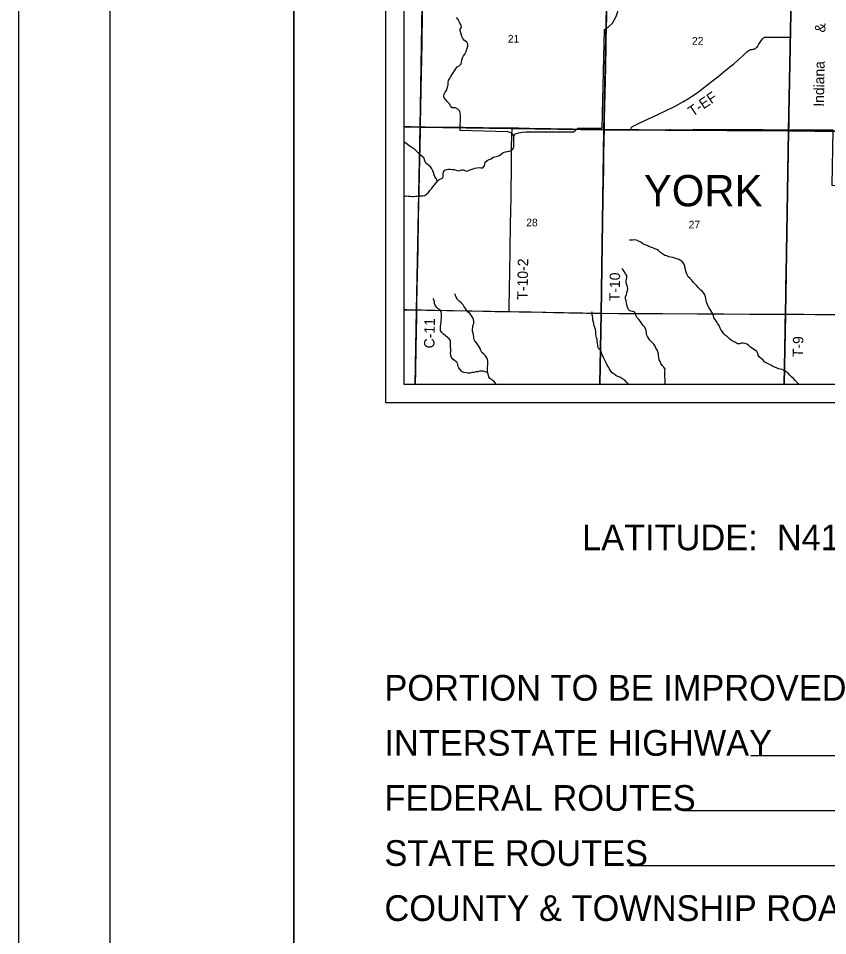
# Model space of a CAD drawing. Extents: x 0 to 42, y 0 to 22.
# Drawn here: x 0 to 4.409, y 11.097 to 16.093 of the extents above; entities that cross this region are included whole.
import ezdxf

# ---------------------------------------------------------------- set-up
doc = ezdxf.new("R2010")
doc.units = 0
for name, color, linetype in [('Default', 7, 'Continuous'), ('GM_X_County_Road', 7, 'Continuous'), ('GM_X_County_Road_Text', 7, 'Continuous'), ('GM_X_Interchange_Ramps', 7, 'Continuous'), ('GM_X_Minor_River', 7, 'Continuous'), ('GM_X_Rail_Line_Text', 7, 'Continuous'), ('GM_X_Section', 7, 'Continuous'), ('GM_X_Section_Text', 7, 'Continuous'), ('GM_X_Township_Road', 7, 'Continuous'), ('GM_X_Township_Road_Text', 7, 'Continuous'), ('GM_X_Township_Text', 7, 'Continuous'), ('SH_Border', 7, 'Continuous'), ('SH_Cut_Line', 7, 'Continuous'), ('SH_Data', 7, 'Continuous'), ('SH_Text', 7, 'Continuous')]:
    doc.layers.add(name, color=color, linetype=linetype)

msp = doc.modelspace()

# ---------------------------------------------------------------- linework, layer by layer
at = {"layer": 'Default'}
for points in [[(2.1, 16.5057), (2.1, 15.5023), (2.1886, 15.5005), (2.2056, 16.5033)], [(2.1, 15.5023), (2.1, 14.5047), (2.1694, 14.5034), (2.1886, 15.5005)], [(2.1, 14.5047), (2.1, 14.1), (2.1621, 14.1), (2.1694, 14.5034)], [(2.1621, 14.1), (3.1686, 14.1), (3.1749, 14.4863), (2.1694, 14.5034)], [(3.1686, 14.1), (4.1714, 14.1), (4.179, 14.4795), (3.1749, 14.4863)], [(4.1714, 14.1), (5.1749, 14.1), (5.1819, 14.4731), (4.179, 14.4795)]]:
    msp.add_lwpolyline(points, close=True, dxfattribs=at)
at = {"layer": 'GM_X_County_Road'}
for points in [[(2.1907, 15.5024), (2.1914, 15.5243), (2.1926, 15.5989), (2.1946, 15.7077), (2.1992, 15.9595), (2.2004, 16.0154), (2.2015, 16.0651), (2.2023, 16.1211), (2.2044, 16.2423), (2.2053, 16.2858), (2.206, 16.3231), (2.2069, 16.3852), (2.2082, 16.4381), (2.209, 16.4644)], [(2.1, 15.5053), (2.1389, 15.5044), (2.1762, 15.503), (2.1907, 15.5024)], [(2.1712, 14.5055), (2.1716, 14.5423), (2.173, 14.6231), (2.1773, 14.8376), (2.1806, 15.0023), (2.1821, 15.0862), (2.1832, 15.1515), (2.1871, 15.3317), (2.1881, 15.3938), (2.1901, 15.484), (2.1907, 15.5024)], [(2.1907, 15.5024), (2.2174, 15.502), (2.4225, 15.4997), (2.6432, 15.4971), (2.6916, 15.4967)], [(2.6916, 15.4967), (2.696, 15.4966), (2.7239, 15.4961), (2.783, 15.4949), (3.0191, 15.4913), (3.1925, 15.4887)], [(3.1925, 15.4887), (3.2118, 15.4885), (3.3375, 15.4878)], [(3.3375, 15.4878), (3.3796, 15.4876), (3.507, 15.4869), (3.5381, 15.4869), (3.5475, 15.4872), (3.5536, 15.4874), (3.5659, 15.4867), (3.5846, 15.4864), (3.6467, 15.4864), (3.7275, 15.486), (3.8363, 15.4853), (4.0663, 15.4846), (4.1222, 15.4838), (4.1978, 15.484)], [(4.1978, 15.484), (4.272, 15.4831), (4.3155, 15.4829), (4.3683, 15.4821), (4.5237, 15.4804), (4.5922, 15.48), (4.6232, 15.4796), (4.9031, 15.4763), (4.9901, 15.4754), (5.0461, 15.4746), (5.1612, 15.4735), (5.2731, 15.4735), (5.3446, 15.474), (5.4783, 15.4751), (5.6991, 15.4769), (5.7488, 15.4774), (5.8701, 15.4786), (5.9447, 15.4796), (5.9547, 15.4798)], [(2.1, 14.5072), (2.116, 14.5068), (2.1501, 14.5057), (2.1712, 14.5055)], [(2.164, 14.1), (2.1653, 14.1725), (2.1674, 14.303), (2.1702, 14.4678), (2.1712, 14.5055)], [(2.1712, 14.5055), (2.1998, 14.5051), (2.2216, 14.5046), (2.3335, 14.5026), (2.3614, 14.5018), (2.5324, 14.4985), (2.5976, 14.4974), (2.6473, 14.4966), (2.6734, 14.4961)], [(2.6734, 14.4961), (2.6815, 14.4959), (2.7281, 14.4952), (2.7716, 14.4943), (2.7932, 14.494), (2.9176, 14.4915), (2.9984, 14.4901), (3.0978, 14.4882), (3.1757, 14.4867)], [(3.1757, 14.4867), (3.2688, 14.4862), (3.3216, 14.4859), (3.5082, 14.485), (3.6978, 14.484), (3.7444, 14.4837), (3.7848, 14.4837), (3.8128, 14.4834), (3.9837, 14.4826), (4.08, 14.4821), (4.111, 14.4818), (4.1791, 14.4815)], [(4.1791, 14.4815), (4.2477, 14.4811), (4.2788, 14.4811), (4.3409, 14.4806), (4.4031, 14.4801), (4.4621, 14.4799), (4.5461, 14.4791), (4.6145, 14.479), (4.6829, 14.4784), (4.7513, 14.4781), (4.8383, 14.4775), (4.9876, 14.4765), (5.0964, 14.476), (5.2021, 14.4755), (5.2798, 14.4758), (5.4757, 14.4765), (5.6125, 14.4769), (5.6747, 14.4771), (5.8208, 14.477), (5.9265, 14.4775), (5.9296, 14.4775), (5.9383, 14.4777)]]:
    msp.add_lwpolyline(points, dxfattribs=at)
at = {"layer": 'GM_X_Interchange_Ramps'}
msp.add_lwpolyline([(2.1, 18.5138), (2.1, 14.1), (6.182, 14.1), (6.1883, 14.4744), (6.2063, 15.4779), (6.2205, 16.2146)], dxfattribs=at)
at = {"layer": 'GM_X_Minor_River'}
for points in [[(2.699, 15.4505), (2.7058, 15.4647), (2.7257, 15.4696), (2.7455, 15.4741), (2.7645, 15.4756), (2.7816, 15.4752), (3.0251, 15.4747), (3.0476, 15.495), (3.1804, 15.4958), (3.1937, 16.0334), (3.2149, 16.047), (3.2374, 16.0677), (3.2576, 16.1033), (3.2748, 16.1595), (3.2747, 16.2191), (3.2728, 16.2518), (3.2652, 16.2815), (3.2721, 16.3019), (3.2839, 16.3195), (3.3331, 16.3958), (3.3403, 16.4932), (3.36, 16.4927)], [(2.4081, 15.5655), (2.4045, 15.5885), (2.3948, 15.5982), (2.3806, 15.605), (2.3631, 15.606), (2.3535, 15.6173), (2.3462, 15.6288), (2.3381, 15.6389), (2.3292, 15.6493), (2.3192, 15.6605), (2.3187, 15.67), (2.3197, 15.681), (2.326, 15.6907), (2.3319, 15.7009), (2.3364, 15.7129), (2.3401, 15.7238), (2.3411, 15.7337), (2.3417, 15.7435), (2.3438, 15.7545), (2.3482, 15.7643), (2.3557, 15.7762), (2.3616, 15.786), (2.3683, 15.7968), (2.3762, 15.8073), (2.3829, 15.8178), (2.3911, 15.8286), (2.4011, 15.8344), (2.4123, 15.8452), (2.4148, 15.855), (2.4158, 15.8648), (2.4195, 15.878), (2.4251, 15.8885), (2.4325, 15.8982), (2.4385, 15.9091), (2.4414, 15.9204), (2.4443, 15.9306), (2.448, 15.9419), (2.449, 15.9529), (2.4432, 15.9629), (2.4309, 15.9723), (2.4209, 15.9828), (2.4166, 15.9939), (2.411, 16.0145), (2.407, 16.0244), (2.4073, 16.0347), (2.4136, 16.0456), (2.4127, 16.0558), (2.4046, 16.0662), (2.4018, 16.0766), (2.396, 16.0869), (2.3867, 16.0981)], [(2.6984, 15.3935), (2.699, 15.4505), (2.6955, 15.4612), (2.6888, 15.467), (2.6779, 15.4722), (2.667, 15.4747), (2.4076, 15.482), (2.4081, 15.5655)], [(4.6965, 15.0998), (4.6927, 15.1519), (4.6903, 15.1577), (4.686, 15.1604), (4.6788, 15.1601), (4.5688, 15.1618), (4.5678, 15.1808), (4.4327, 15.1827), (4.4387, 15.484), (3.6765, 15.4885)], [(2.2828, 15.2062), (2.2741, 15.222), (2.2694, 15.2316), (2.2658, 15.2415), (2.2623, 15.253), (2.2587, 15.263), (2.2533, 15.2745), (2.2444, 15.2845), (2.2352, 15.2942), (2.2255, 15.3017), (2.2155, 15.3114), (2.2131, 15.3228), (2.2103, 15.3324), (2.2002, 15.3402), (2.1898, 15.3495), (2.1805, 15.3592), (2.1701, 15.3682), (2.1594, 15.3783), (2.1489, 15.3861), (2.1287, 15.3995), (2.1175, 15.4073), (2.1056, 15.4163), (2.1, 15.4203)], [(2.1, 15.1223), (2.101, 15.1226), (2.1128, 15.1262), (2.1238, 15.1244), (2.1337, 15.1242), (2.1435, 15.1236), (2.1534, 15.1237), (2.1629, 15.1243), (2.1735, 15.1252), (2.1853, 15.1257), (2.1948, 15.1259), (2.2043, 15.1264), (2.2142, 15.1288), (2.2242, 15.1351), (2.2351, 15.1443), (2.2414, 15.1548), (2.25, 15.1652), (2.2582, 15.1761), (2.2668, 15.1861), (2.275, 15.1962), (2.2828, 15.2062), (2.2917, 15.2159), (2.3024, 15.2187), (2.3124, 15.2246), (2.3146, 15.2348), (2.314, 15.2446), (2.3166, 15.2564), (2.3229, 15.2665), (2.3329, 15.27), (2.3428, 15.2725), (2.3537, 15.2711), (2.3636, 15.2705), (2.3746, 15.2706), (2.3851, 15.2658), (2.3949, 15.2626), (2.4056, 15.2654), (2.4151, 15.2686), (2.425, 15.2683), (2.4355, 15.262), (2.4457, 15.2618), (2.4564, 15.2657), (2.4675, 15.2704), (2.4775, 15.2729), (2.4874, 15.2772), (2.4977, 15.2789), (2.5103, 15.2809), (2.5201, 15.2795), (2.5296, 15.2793), (2.5385, 15.2889), (2.5414, 15.2991), (2.5436, 15.3093), (2.5537, 15.3186), (2.564, 15.3241), (2.5763, 15.3283), (2.5863, 15.3368), (2.5963, 15.3397), (2.61, 15.3431), (2.6219, 15.3471), (2.6319, 15.3552), (2.6416, 15.3618), (2.6534, 15.3657), (2.6637, 15.3689), (2.6732, 15.3698), (2.6836, 15.373), (2.6936, 15.3811), (2.6984, 15.3935)], [(4.1936, 14.1609), (4.1835, 14.1687), (4.1738, 14.1731), (4.1614, 14.1798), (4.1512, 14.1831), (4.1406, 14.1844), (4.1294, 14.1889), (4.1196, 14.1933), (4.1091, 14.1992), (4.0986, 14.2044), (4.0889, 14.2099), (4.0772, 14.2151), (4.0664, 14.2214), (4.0575, 14.2311), (4.0463, 14.2397), (4.0367, 14.2486), (4.0308, 14.2583), (4.0292, 14.2682), (4.0226, 14.2793), (4.011, 14.2876), (4.0009, 14.2935), (3.9894, 14.3028), (3.9782, 14.313), (3.9685, 14.3177), (3.9587, 14.3221), (3.9482, 14.3243), (3.9387, 14.3241), (3.9283, 14.3205), (3.9185, 14.3211), (3.9076, 14.3271), (3.8956, 14.3338), (3.8844, 14.3394), (3.8732, 14.3495), (3.8636, 14.358), (3.8531, 14.3651), (3.8435, 14.3756), (3.8362, 14.3856), (3.8295, 14.3953), (3.8233, 14.4053), (3.8176, 14.4194), (3.8102, 14.4291), (3.8033, 14.4414), (3.7967, 14.4522), (3.7883, 14.4626), (3.787, 14.4733), (3.7838, 14.4832), (3.7784, 14.4932), (3.7718, 14.5028), (3.7656, 14.5136), (3.7586, 14.5255), (3.7551, 14.5355), (3.7493, 14.5466), (3.7472, 14.5562), (3.7452, 14.5668), (3.7431, 14.5771), (3.7392, 14.5875), (3.7341, 14.5971), (3.7256, 14.6067), (3.716, 14.6153), (3.706, 14.6262), (3.6967, 14.6366), (3.6867, 14.6452), (3.6774, 14.6549), (3.6682, 14.6665), (3.659, 14.6766), (3.6493, 14.6855), (3.6431, 14.6959), (3.6392, 14.7062), (3.6368, 14.7165), (3.6336, 14.7261), (3.6312, 14.736), (3.6314, 14.7467), (3.6256, 14.757), (3.6186, 14.7667), (3.6074, 14.7749), (3.5973, 14.7789), (3.5871, 14.7826), (3.5762, 14.787), (3.5656, 14.7899), (3.5551, 14.7916), (3.543, 14.7938), (3.5325, 14.8001), (3.5215, 14.8023), (3.5085, 14.8109), (3.4988, 14.8187), (3.488, 14.8281), (3.4779, 14.8336), (3.467, 14.8376), (3.4557, 14.8428), (3.4452, 14.8473), (3.4354, 14.8513), (3.4253, 14.856), (3.414, 14.8597), (3.402, 14.8653), (3.3908, 14.8739), (3.3792, 14.8802), (3.3668, 14.8847), (3.3558, 14.8865), (3.3463, 14.8859), (3.3361, 14.885), (3.3292, 14.8848)], [(3.5236, 14.1), (3.5238, 14.1053), (3.5236, 14.1166), (3.5239, 14.1284), (3.5227, 14.1402), (3.5218, 14.152), (3.5213, 14.1615), (3.5211, 14.1717), (3.5233, 14.1823), (3.5159, 14.1927), (3.5071, 14.2032), (3.5009, 14.2136), (3.4958, 14.2239), (3.4919, 14.2335), (3.4895, 14.2442), (3.4882, 14.256), (3.4866, 14.2663), (3.4838, 14.2774), (3.481, 14.2869), (3.4736, 14.2969), (3.4686, 14.3077), (3.4616, 14.3181), (3.4509, 14.329), (3.4405, 14.3398), (3.4343, 14.3498), (3.4266, 14.3606), (3.4215, 14.3706), (3.4214, 14.3812), (3.4204, 14.3911), (3.4188, 14.4007), (3.4115, 14.4122), (3.4026, 14.4223), (3.3956, 14.4327), (3.3894, 14.4423), (3.3802, 14.4532), (3.3702, 14.4636), (3.3655, 14.4736), (3.3619, 14.4832), (3.3576, 14.4928), (3.3471, 14.4968), (3.3361, 14.4982), (3.3264, 14.5045), (3.3202, 14.5149), (3.3174, 14.5248), (3.3149, 14.5343), (3.3133, 14.5443), (3.3104, 14.5538), (3.3084, 14.5656), (3.3079, 14.5763), (3.3128, 14.5883), (3.3153, 14.5996), (3.3179, 14.6106), (3.3204, 14.6204), (3.3187, 14.6311), (3.314, 14.6418), (3.312, 14.6521), (3.3119, 14.662), (3.3125, 14.6726), (3.3142, 14.6824), (3.3141, 14.6919), (3.3079, 14.7023), (3.3002, 14.7135), (3.294, 14.7239), (3.2873, 14.7316)], [(2.6027, 14.1), (2.5984, 14.1075), (2.5896, 14.1171), (2.5791, 14.1238), (2.569, 14.1309), (2.5624, 14.1409), (2.5589, 14.1531), (2.5569, 14.1627), (2.5556, 14.1726), (2.5555, 14.1832), (2.5557, 14.1935), (2.5571, 14.2037), (2.5581, 14.2139), (2.5576, 14.2253), (2.5567, 14.2352), (2.552, 14.2448), (2.545, 14.2544), (2.5361, 14.2641), (2.5253, 14.2735), (2.5195, 14.2838), (2.5156, 14.2942), (2.5105, 14.3045), (2.5035, 14.3146), (2.4954, 14.325), (2.487, 14.3362), (2.4815, 14.347), (2.4806, 14.3576), (2.4798, 14.369), (2.4777, 14.3789), (2.4734, 14.39), (2.4737, 14.401), (2.4766, 14.4112), (2.4757, 14.4207), (2.4805, 14.432), (2.4811, 14.443), (2.4791, 14.4529), (2.4759, 14.4629), (2.4682, 14.4729), (2.4605, 14.4837), (2.4508, 14.4923), (2.4416, 14.5031), (2.4365, 14.5127), (2.4287, 14.5224), (2.4237, 14.5324), (2.4133, 14.5425), (2.4006, 14.5522), (2.3929, 14.5627), (2.386, 14.5746), (2.3798, 14.5888), (2.378, 14.5922)], [(2.5539, 14.1646), (2.5437, 14.1675), (2.5332, 14.1708), (2.5229, 14.1707), (2.5127, 14.1709), (2.5027, 14.1681), (2.4933, 14.1683), (2.4814, 14.1651), (2.4708, 14.1635), (2.4605, 14.1614), (2.4506, 14.1613), (2.4389, 14.1623), (2.4275, 14.1641), (2.4155, 14.1693), (2.4066, 14.1797), (2.4004, 14.1901), (2.395, 14.1997), (2.3941, 14.21), (2.3886, 14.2204), (2.3782, 14.2282), (2.367, 14.2368), (2.3597, 14.2464), (2.3557, 14.2572), (2.3549, 14.2689), (2.3559, 14.2792), (2.3569, 14.2917), (2.3545, 14.3035), (2.3541, 14.3179), (2.3544, 14.3278), (2.3542, 14.3377), (2.3461, 14.3485), (2.3361, 14.3563), (2.3264, 14.3645), (2.3164, 14.3738), (2.3067, 14.3824), (2.2997, 14.3932), (2.3004, 14.4034), (2.3006, 14.4148), (2.3017, 14.4262), (2.3031, 14.4386), (2.3034, 14.45), (2.3044, 14.4622), (2.3046, 14.472), (2.3053, 14.4845), (2.304, 14.4944), (2.2978, 14.5044), (2.2877, 14.5111), (2.2773, 14.5205), (2.2707, 14.5301), (2.2679, 14.5396), (2.2662, 14.5496), (2.2638, 14.5595), (2.2595, 14.5676)], [(3.3236, 14.1), (3.3215, 14.1026), (3.3133, 14.1123), (3.3041, 14.122), (3.2869, 14.1314), (3.2764, 14.1397), (3.2655, 14.1426), (3.2558, 14.1481), (3.246, 14.1544), (3.2356, 14.1618), (3.2279, 14.1723), (3.2205, 14.1819), (3.2162, 14.1915), (3.2085, 14.2038), (3.2042, 14.2138), (3.198, 14.2249), (3.1926, 14.2353), (3.1879, 14.2457), (3.1835, 14.2552), (3.1792, 14.266), (3.1764, 14.2755), (3.1717, 14.2859), (3.162, 14.2933), (3.1577, 14.3033), (3.1568, 14.3128), (3.1555, 14.3234), (3.1535, 14.3337), (3.1537, 14.3436), (3.1498, 14.3539), (3.1474, 14.3646), (3.1465, 14.3745), (3.1464, 14.3863), (3.1436, 14.3977), (3.1412, 14.4088), (3.1369, 14.4188), (3.1349, 14.4283), (3.1329, 14.4394), (3.1304, 14.4489), (3.1296, 14.4603), (3.1279, 14.4706), (3.1262, 14.4805), (3.1257, 14.4904), (3.1243, 14.4954)], [(4.2513, 14.1), (4.2421, 14.1093), (4.2325, 14.1205), (4.2225, 14.1317), (4.2121, 14.1407), (4.2024, 14.15), (4.1936, 14.1609)]]:
    msp.add_lwpolyline(points, dxfattribs=at)
at = {"layer": 'GM_X_Section'}
for points in [[(2.2056, 16.5033), (3.2111, 16.4878), (3.1895, 15.4854), (2.1886, 15.5005)], [(3.2111, 16.4878), (4.2153, 16.4855), (4.1963, 15.4797), (3.1895, 15.4854)], [(4.2153, 16.4855), (5.2156, 16.4769), (5.2026, 15.4687), (4.1963, 15.4797)], [(3.1895, 15.4854), (3.1749, 14.4863), (2.1694, 14.5034), (2.1886, 15.5005)], [(4.1963, 15.4797), (4.179, 14.4795), (3.1749, 14.4863), (3.1895, 15.4854)], [(5.2026, 15.4687), (5.1819, 14.4731), (4.179, 14.4795), (4.1963, 15.4797)]]:
    msp.add_lwpolyline(points, close=True, dxfattribs=at)
at = {"layer": 'GM_X_Township_Road'}
for points in [[(3.1925, 15.4887), (3.1938, 15.5436), (3.1954, 15.615), (3.1966, 15.6834), (3.1999, 15.8264), (3.2025, 15.9476), (3.2029, 15.9881), (3.2039, 16.0316), (3.2057, 16.1155), (3.208, 16.2274), (3.2088, 16.2647), (3.2109, 16.3672), (3.2131, 16.4729), (3.2134, 16.4891)], [(4.2067, 15.9906), (4.2077, 16.0508), (4.2089, 16.1037), (4.2128, 16.2964), (4.2153, 16.4331), (4.2165, 16.4875)], [(3.8836, 15.835), (3.8951, 15.8446), (3.9305, 15.875), (3.9466, 15.8896), (3.9693, 15.9109), (3.9741, 15.9149), (3.9766, 15.9167), (3.9819, 15.9199), (3.9846, 15.9213), (3.9876, 15.9225), (3.9895, 15.9231), (3.9917, 15.9237), (3.997, 15.9245), (4.0031, 15.9252), (4.0059, 15.9256), (4.0076, 15.9259), (4.0093, 15.9264), (4.0124, 15.9275), (4.0153, 15.9289), (4.0181, 15.9308), (4.02, 15.9325), (4.0219, 15.9347), (4.024, 15.937), (4.0279, 15.9419), (4.0348, 15.9523), (4.0498, 15.9759), (4.0534, 15.981), (4.0554, 15.9833), (4.0576, 15.9855), (4.0601, 15.9873), (4.0628, 15.9888), (4.0657, 15.9899), (4.0687, 15.9906), (4.0717, 15.9911), (4.078, 15.9913), (4.1028, 15.9911), (4.1899, 15.9906), (4.1992, 15.9906), (4.2067, 15.9906)], [(4.1978, 15.484), (4.1984, 15.5099), (4.1987, 15.5285), (4.1989, 15.5471), (4.1993, 15.5751), (4.1998, 15.6218), (4.201, 15.6684), (4.2017, 15.715), (4.2034, 15.8176), (4.2046, 15.8736), (4.2051, 15.8984), (4.2067, 15.9906)], [(3.3375, 15.4878), (3.338, 15.4917), (3.3385, 15.4948), (3.3393, 15.4978), (3.341, 15.5003), (3.3434, 15.5022), (3.3459, 15.5039), (3.3596, 15.5114), (3.3848, 15.5237), (3.4526, 15.5548), (3.5594, 15.6054), (3.5788, 15.6151), (3.5952, 15.624), (3.6194, 15.6379), (3.6514, 15.6572), (3.6724, 15.6705), (3.693, 15.6844), (3.7132, 15.6989), (3.733, 15.714), (3.7818, 15.7524), (3.8112, 15.7754), (3.8474, 15.8047), (3.8836, 15.835)], [(2.1, 15.5053), (2.1389, 15.5044), (2.1762, 15.503), (2.1907, 15.5024)], [(2.1907, 15.5024), (2.2174, 15.502), (2.4225, 15.4997), (2.6432, 15.4971), (2.6916, 15.4967)], [(2.6839, 15.0886), (2.6848, 15.1328), (2.6851, 15.1639), (2.6862, 15.2572), (2.687, 15.3256), (2.687, 15.3691), (2.687, 15.4034), (2.6878, 15.4407), (2.6888, 15.4625), (2.6904, 15.4842), (2.6907, 15.4873), (2.6916, 15.4967)], [(2.6916, 15.4967), (2.696, 15.4966), (2.7239, 15.4961), (2.783, 15.4949), (3.0191, 15.4913), (3.1925, 15.4887)], [(3.1757, 14.4867), (3.1763, 14.5302), (3.1817, 14.8535), (3.1848, 15.0524), (3.1887, 15.2732), (3.19, 15.3477), (3.1912, 15.4348), (3.1925, 15.4887)], [(3.1925, 15.4887), (3.2118, 15.4885), (3.3375, 15.4878)], [(3.3375, 15.4878), (3.3796, 15.4876), (3.507, 15.4869), (3.5381, 15.4869), (3.5475, 15.4872), (3.5536, 15.4874), (3.5659, 15.4867), (3.5846, 15.4864), (3.6467, 15.4864), (3.7275, 15.486), (3.8363, 15.4853), (4.0663, 15.4846), (4.1222, 15.4838), (4.1978, 15.484)], [(4.1791, 14.4815), (4.1808, 14.5804), (4.1818, 14.6271), (4.1831, 14.7048), (4.1837, 14.7328), (4.1844, 14.7794), (4.187, 14.9131), (4.1877, 14.9535), (4.1885, 14.9908), (4.189, 15.0374), (4.1918, 15.1773), (4.1924, 15.2178), (4.1949, 15.339), (4.1956, 15.3732), (4.1978, 15.484)], [(4.1978, 15.484), (4.272, 15.4831), (4.3155, 15.4829), (4.3683, 15.4821), (4.5237, 15.4804), (4.5922, 15.48), (4.6232, 15.4796), (4.9031, 15.4763), (4.9901, 15.4754), (5.0461, 15.4746), (5.1612, 15.4735), (5.2731, 15.4735), (5.3446, 15.474), (5.4783, 15.4751), (5.6991, 15.4769), (5.7488, 15.4774), (5.8701, 15.4786), (5.9447, 15.4796), (5.9547, 15.4798)], [(2.6734, 14.4961), (2.6735, 14.5045), (2.6756, 14.6351), (2.6766, 14.6973), (2.6794, 14.8466), (2.6812, 14.9555), (2.6817, 14.9897), (2.6826, 15.027), (2.6835, 15.0706), (2.6839, 15.0886)], [(3.1682, 14.1), (3.1707, 14.2287), (3.1733, 14.3686), (3.1748, 14.4338), (3.1757, 14.4867)], [(4.1726, 14.1), (4.1728, 14.114), (4.1736, 14.1514), (4.1745, 14.1918), (4.1754, 14.2478), (4.1758, 14.2757), (4.1763, 14.313), (4.1772, 14.3752), (4.1783, 14.4343), (4.1791, 14.4815)]]:
    msp.add_lwpolyline(points, dxfattribs=at)
at = {"layer": 'SH_Border'}
for points in [[(0.5, 21.5), (1.5, 21.5), (1.5, 0.5), (0.5, 0.5)], [(1.5, 21.5), (33.5, 21.5), (33.5, 0.5), (1.5, 0.5)]]:
    msp.add_lwpolyline(points, close=True, dxfattribs=at)
at = {"layer": 'SH_Cut_Line'}
msp.add_lwpolyline([(0, 0), (34, 0), (34, 22), (0, 22)], close=True, dxfattribs=at)
at = {"layer": 'SH_Data'}
for p, q in [((2, 21), (2, 14)), ((2.1, 20.9), (2.1, 14.1)), ((2.1, 14.1), (8.9, 14.1)), ((2.1, 14.1), (2.1, 14.1)), ((2, 14), (9, 14)), ((7.7, 12.0767), (3.9895, 12.0767)), ((7.7, 11.7767), (3.6192, 11.7767)), ((7.7, 11.4767), (3.3288, 11.4767))]:
    msp.add_line(p, q, dxfattribs=at)

# ---------------------------------------------------------------- texts
at = {"layer": 'GM_X_County_Road_Text'}
msp.add_text('C-11', height=0.05682, rotation=88.9714, dxfattribs=at).set_placement((2.2666, 14.2953))
at = {"layer": 'GM_X_Rail_Line_Text'}
for s, height, rotation, p in [('&', 0.0566, 88.666, (4.396, 16.0159)), ('Indiana', 0.05663, 88.9677, (4.3882, 15.6115))]:
    msp.add_text(s, height=height, rotation=rotation, dxfattribs=at).set_placement(p)
at = {"layer": 'GM_X_Section_Text'}
for s, p in [('21', (2.6666, 15.9616)), ('22', (3.6699, 15.9499)), ('28', (2.767, 14.9604)), ('27', (3.6516, 14.9488))]:
    msp.add_text(s, height=0.04186, rotation=0, dxfattribs=at).set_placement(p)
at = {"layer": 'GM_X_Township_Road_Text'}
for s, rotation, p in [('T-EF', 34.2483, (3.673, 15.5562)), ('T-10-2', 89.0099, (2.774, 14.5607)), ('T-10', 88.9383, (3.2756, 14.5519)), ('T-9', 89.04, (4.2748, 14.2476))]:
    msp.add_text(s, height=0.05682, rotation=rotation, dxfattribs=at).set_placement(p)
at = {"layer": 'GM_X_Township_Text'}
msp.add_text('YORK', height=0.17045, rotation=0, dxfattribs=at).set_placement((3.4078, 15.0696))
at = {"layer": 'SH_Text'}
for s, p in [('LATITUDE:  N41°34\'26"     LONGITUDE:  W84°00\'56"', (3.071, 13.1959)), ('PORTION TO BE IMPROVED', (1.9944, 12.3767)), ('INTERSTATE HIGHWAY', (1.9944, 12.0767)), ('FEDERAL ROUTES', (1.9944, 11.7767)), ('STATE ROUTES', (1.9944, 11.4767)), ('COUNTY & TOWNSHIP ROADS', (1.9944, 11.1767))]:
    msp.add_text(s, height=0.14, dxfattribs=at).set_placement(p)

doc.saveas('drawing.dxf')
